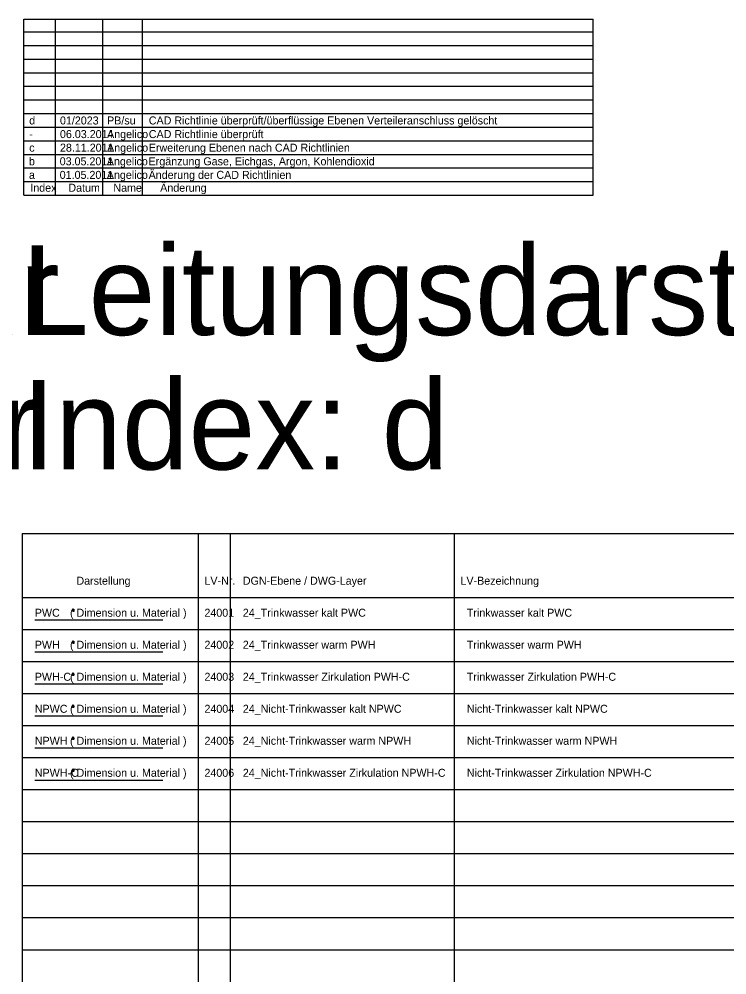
# Model space of a CAD drawing. Extents: x -14.5 to 23.8, y -56.3 to 8.
# Drawn here: x -0.05 to 11.01, y -6.89 to 8.03 of the extents above; entities that cross this region are included whole.
import ezdxf

# ---------------------------------------------------------------- set-up
doc = ezdxf.new("R2010")
doc.units = 0
for name, color, linetype in [('24_Nicht-Trinkwasser kalt NPWC', 7, 'Continuous'), ('24_Nicht-Trinkwasser warm NPWH', 7, 'Continuous'), ('24_Nicht-Trinkwasser Zirkulation NPWH-C', 7, 'Continuous'), ('24_Trinkwasser kalt PWC', 7, 'Continuous'), ('24_Trinkwasser warm PWH', 7, 'Continuous'), ('24_Trinkwasser Zirkulation PWH-C', 7, 'Continuous'), ('Default', 7, 'Continuous')]:
    doc.layers.add(name, color=color, linetype=linetype)

msp = doc.modelspace()

# ---------------------------------------------------------------- linework, layer by layer
at = {"layer": '24_Nicht-Trinkwasser kalt NPWC'}
for p, q in [((0.784, -2.684), (0.816, -2.716)), ((0.816, -2.684), (0.784, -2.716)), ((0.8, -2.678), (0.8, -2.722)), ((0.778, -2.7), (0.822, -2.7)), ((0.2, -2.85), (2.2, -2.85))]:
    msp.add_line(p, q, dxfattribs=at)
at = {"layer": '24_Nicht-Trinkwasser warm NPWH'}
for p, q in [((0.778, -3.2), (0.822, -3.2)), ((0.784, -3.184), (0.816, -3.216)), ((0.816, -3.184), (0.784, -3.216)), ((0.8, -3.178), (0.8, -3.222)), ((0.2, -3.35), (2.2, -3.35))]:
    msp.add_line(p, q, dxfattribs=at)
at = {"layer": '24_Nicht-Trinkwasser Zirkulation NPWH-C'}
for p, q in [((0.778, -3.7), (0.822, -3.7)), ((0.784, -3.684), (0.816, -3.716)), ((0.816, -3.684), (0.784, -3.716)), ((0.8, -3.678), (0.8, -3.722)), ((0.2, -3.85), (2.2, -3.85))]:
    msp.add_line(p, q, dxfattribs=at)
at = {"layer": '24_Trinkwasser kalt PWC'}
for p, q in [((0.784, -1.184), (0.816, -1.216)), ((0.816, -1.184), (0.784, -1.216)), ((0.8, -1.178), (0.8, -1.222)), ((0.778, -1.2), (0.822, -1.2)), ((0.2, -1.35), (2.2, -1.35))]:
    msp.add_line(p, q, dxfattribs=at)
at = {"layer": '24_Trinkwasser warm PWH'}
for p, q in [((0.778, -1.7), (0.822, -1.7)), ((0.784, -1.684), (0.816, -1.716)), ((0.816, -1.684), (0.784, -1.716)), ((0.8, -1.678), (0.8, -1.722)), ((0.2, -1.85), (2.2, -1.85))]:
    msp.add_line(p, q, dxfattribs=at)
at = {"layer": '24_Trinkwasser Zirkulation PWH-C'}
for p, q in [((0.778, -2.2), (0.822, -2.2)), ((0.784, -2.184), (0.816, -2.216)), ((0.816, -2.184), (0.784, -2.216)), ((0.8, -2.178), (0.8, -2.222)), ((0.2, -2.35), (2.2, -2.35))]:
    msp.add_line(p, q, dxfattribs=at)
at = {"layer": 'Default'}
for p, q in [((0.029, 5.285), (0.029, 8.034)), ((0.029, 8.034), (8.923, 8.034)), ((0.523, 5.285), (0.523, 8.034)), ((1.264, 5.285), (1.264, 8.034)), ((1.882, 5.285), (1.882, 8.034)), ((8.923, 5.285), (8.923, 8.034)), ((0.029, 7.835), (8.923, 7.835)), ((0.029, 7.622), (8.923, 7.622)), ((0.029, 7.41), (8.923, 7.41)), ((0.029, 7.197), (8.923, 7.197)), ((0.029, 6.985), (8.923, 6.985)), ((0.029, 6.772), (8.923, 6.772)), ((0.029, 6.56), (8.923, 6.56)), ((0.029, 6.347), (8.923, 6.347)), ((0.029, 6.135), (8.923, 6.135)), ((0.029, 5.922), (8.923, 5.922)), ((0.029, 5.71), (8.923, 5.71)), ((0.029, 5.497), (8.923, 5.497)), ((0.029, 5.285), (8.923, 5.285)), ((0.029, 5.285), (8.923, 5.285)), ((0, 0), (0, -53.5)), ((0, 0), (16, 0)), ((2.75, 0), (2.75, -53.5)), ((3.25, 0), (3.25, -53.5)), ((6.75, 0), (6.75, -53.5)), ((0, -1), (14.169, -1)), ((0, -1), (16, -1)), ((0, -1.5), (16, -1.5)), ((0, -2), (16, -2)), ((0, -2.5), (16, -2.5)), ((0, -3), (16, -3)), ((0, -3.5), (16, -3.5)), ((0, -4), (16, -4)), ((0, -4.5), (16, -4.5)), ((0, -5), (16, -5)), ((0, -5.5), (16, -5.5)), ((0, -6), (16, -6)), ((0, -6.5), (16, -6.5))]:
    msp.add_line(p, q, dxfattribs=at)

# ---------------------------------------------------------------- texts
at = {"layer": '24_Nicht-Trinkwasser kalt NPWC'}
for s, p in [('NPWC', (0.2, -2.8)), ('( Dimension u. Material )', (0.75, -2.8))]:
    msp.add_text(s, height=0.125, dxfattribs=at).set_placement(p)
at = {"layer": '24_Nicht-Trinkwasser warm NPWH'}
for s, p in [('NPWH', (0.2, -3.3)), ('( Dimension u. Material )', (0.75, -3.3))]:
    msp.add_text(s, height=0.125, dxfattribs=at).set_placement(p)
at = {"layer": '24_Nicht-Trinkwasser Zirkulation NPWH-C'}
for s, p in [('NPWH-C', (0.2, -3.8)), ('( Dimension u. Material )', (0.75, -3.8))]:
    msp.add_text(s, height=0.125, dxfattribs=at).set_placement(p)
at = {"layer": '24_Trinkwasser kalt PWC'}
for s, p in [('PWC', (0.2, -1.3)), ('( Dimension u. Material )', (0.75, -1.3))]:
    msp.add_text(s, height=0.125, dxfattribs=at).set_placement(p)
at = {"layer": '24_Trinkwasser warm PWH'}
for s, p in [('PWH', (0.2, -1.8)), ('( Dimension u. Material )', (0.75, -1.8))]:
    msp.add_text(s, height=0.125, dxfattribs=at).set_placement(p)
at = {"layer": '24_Trinkwasser Zirkulation PWH-C'}
for s, p in [('PWH-C', (0.2, -2.3)), ('( Dimension u. Material )', (0.75, -2.3))]:
    msp.add_text(s, height=0.125, dxfattribs=at).set_placement(p)
at = {"layer": 'Default'}
for s, height, p in [('d     ', 0.125, (0.113, 6.389)), ('01/2023   ', 0.125, (0.593, 6.389)), ('PB/su   ', 0.125, (1.329, 6.389)), ('CAD Richtlinie überprüft/überflüssige Ebenen Verteileranschluss gelöscht                        ', 0.125, (1.981, 6.389)), ('06.03.2014', 0.125, (0.593, 6.176)), ('Angelico', 0.125, (1.329, 6.176)), ('CAD Richtlinie überprüft                                                                        ', 0.125, (1.981, 6.176)), ('-     ', 0.125, (0.113, 6.176)), ('c     ', 0.125, (0.113, 5.964)), ('28.11.2011', 0.125, (0.593, 5.964)), ('Angelico', 0.125, (1.329, 5.964)), ('Erweiterung Ebenen nach CAD Richtlinien                                                         ', 0.125, (1.981, 5.964)), ('b     ', 0.125, (0.109, 5.751)), ('03.05.2011', 0.125, (0.589, 5.751)), ('Angelico', 0.125, (1.325, 5.751)), ('Ergänzung Gase, Eichgas, Argon, Kohlendioxid                                                    ', 0.125, (1.978, 5.751)), ('Änderung der CAD Richtlinien                                                                    ', 0.125, (1.978, 5.539)), ('a     ', 0.125, (0.109, 5.539)), ('01.05.2011', 0.125, (0.589, 5.539)), ('Angelico', 0.125, (1.325, 5.539)), ('Index', 0.125, (0.13, 5.338)), ('Datum', 0.125, (0.724, 5.338)), ('Name', 0.125, (1.427, 5.338)), ('Änderung', 0.125, (2.159, 5.338)), ('Musterlegende für ', 1.4, (-14.5, 3.1)), ('Leitungsdarstellung: Sanitär', 1.4, (0, 3.1)), ('Blattpläne Sanitär', 1.4, (-14.5, 1)), ('Index: d', 1.4, (0, 1)), ('Darstellung', 0.125, (0.85, -0.8)), ('LV-Nr.', 0.125, (2.85, -0.8)), ('DGN-Ebene / DWG-Layer', 0.125, (3.45, -0.8)), ('LV-Bezeichnung', 0.125, (6.85, -0.8)), ('24001', 0.125, (2.85, -1.3)), ('24_Trinkwasser kalt PWC', 0.125, (3.45, -1.3)), ('Trinkwasser kalt PWC', 0.125, (6.95, -1.3)), ('24002', 0.125, (2.85, -1.8)), ('24_Trinkwasser warm PWH', 0.125, (3.45, -1.8)), ('Trinkwasser warm PWH', 0.125, (6.95, -1.8)), ('24003', 0.125, (2.85, -2.3)), ('24_Trinkwasser Zirkulation PWH-C', 0.125, (3.45, -2.3)), ('Trinkwasser Zirkulation PWH-C', 0.125, (6.95, -2.3)), ('24004', 0.125, (2.85, -2.8)), ('24_Nicht-Trinkwasser kalt NPWC', 0.125, (3.45, -2.8)), ('Nicht-Trinkwasser kalt NPWC', 0.125, (6.95, -2.8)), ('24005', 0.125, (2.85, -3.3)), ('24_Nicht-Trinkwasser warm NPWH', 0.125, (3.45, -3.3)), ('Nicht-Trinkwasser warm NPWH', 0.125, (6.95, -3.3)), ('24006', 0.125, (2.85, -3.8)), ('24_Nicht-Trinkwasser Zirkulation NPWH-C', 0.125, (3.45, -3.8)), ('Nicht-Trinkwasser Zirkulation NPWH-C', 0.125, (6.95, -3.8))]:
    msp.add_text(s, height=height, dxfattribs=at).set_placement(p)

doc.saveas('drawing.dxf')
